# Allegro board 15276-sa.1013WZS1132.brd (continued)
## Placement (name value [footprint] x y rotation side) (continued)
U3602  LR9102G-15-AE5-R-GP  [SOT-23-2924-5PH46]  150.86 25.41 180 bottom
U3603  G5016KD1U-GP  [DFN14J3020-G255D85H32]  145.78 77.1 90 bottom
U5201  RT9724GB-GP  [SOT-23-5H51]  103.22 153.2 180 top
U5601  TPS2001CDGNR-GP  [MSOP8-1G189157H43]  166.99 85.1 180 bottom
U5603  TC74VHCT125AFTQK2M-GP  [TSOIC14H48]  33.76 70.37 270 top
USB1  SKT-USB13-111-GP-U  [SKT-USB13-160166-7]  5.27 39.97 90 bottom
WLAN1  SKT-MINI67P-12-GP-U  [NFSA0-S6705-TP40]  168.6 53.77 90 bottom
X601  XTAL-32D768KHZ-67-GP  [SMD49-6914-0403H56]  128.51 106.31 0 bottom
X1902  XTAL-48MHZ-27-GP-U  [OSC-3225-4P-4H36]  111.89 103.26 180 bottom
X3001  XTAL-25MHZ-155-GP  [OSC-3225-4P-3H36]  49 176.41 180 top
XF3101  XFORM-12P-48-GP  [XFORM12A127097H91]  24.21 169.15 90 bottom
XF3102  XFORM-12P-48-GP  [XFORM12A127097H91]  24.21 169.15 270 top

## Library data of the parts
AFTP2501 AFTP2502 AFTP2801-AFTP2803 AFTP2901-AFTP2904 AFTP3101-AFTP3108 AFTP3301-AFTP3310 AFTP3401-AFTP3403 AFTP3801-AFTP3803 AFTP3805 AFTP3806 AFTP3901-AFTP3910 AFTP5201-AFTP5214 AFTP5227 AFTP5601 AFTP5801-AFTP5807 AFTP6101-AFTP6104 AFTP6201-AFTP6203 AFTP6206-AFTP6208 AFTP6213-AFTP6242 AFTP6245-AFTP6248 AFTP6301-AFTP6307 AFTP6309-AFTP6311 AFTP6313 AFTP6314 = AFTE14P-75: tolerance: ZZ.AFT14.101
BATT1 = 200277MR008G121ZR-U: tolerance: 20.81153.008
C1-C3 = HOLE197R166: tolerance: ZZ.00PAD.V71
C303-C306 C443 C3202 C3205 C3301 C3403-C3406 C3519 C5401 C5604 C5606 C5801-C5804 C6205 EC6106 EC6107 PC4508 PC4516 PC4607 PC4619 = C402H22: tolerance: 78.10421.2FL
C401 C402 C601 = C402H22: tolerance: 78.15124.2FL
C501 C1201 C1204 C1214 C1217 C1222-C1225 C1330 C1334-C1337 C1342 C1344 C1346 C2402-C2404 C2406-C2410 C2412 C2414 C2417 C2502 C2602 C2605 C2608-C2610 C2615 C2707 C2709 C2710 C2717 C2719 C2720 C3002 C3009 C3013 C3014 C3016 C3507 C3625 C3626 C5201 C5203 C5209-C5213 C5402-C5409 C6202-C6204 EC2601 EC2703 EC2705 EC2708 EC2709 EC9739 EC9743 EC9744 PC4906 = C402H22: tolerance: 78.10423.2FL
C502 C1203 C1205 C1221 C1307 C1333 C1345 C3601 C3602 C3618 C3619 C5202 EC2704 EC2706 EC2707 EC6101 EC9707 EC9709-EC9711 EC9714 EC9745 PC4601 PC4605 PC4606 PC4622 PC4660 PC4742 PC4743 PC4831 = C402H22: tolerance: 78.10224.2FL
C603 C604 C3001 C3011 = C402H22: tolerance: 78.15034.1FL
C701 C702 C705 C3505 C3508 C3510 PC4901 PC4904 = C603H36: tolerance: 78.10523.5BL
C703 C762 C1208 C1331 C2501 C2601 C2712 C2713 C2901 C2907 C2908 C3603 C3605 C3620 C3621 C5805 C5806 PC4916 PC4917 PC5010-PC5012 PC5015 = C603H38: tolerance: 78.10610.5BL
C704 C1004-C1009 C1012-C1014 C1026-C1032 C1035-C1037 C1040-C1045 C1093-C1096 C1209-C1212 C1338-C1341 C2416 C2418 C5206 EC9718-EC9728 EC9732-EC9738 EC9759-EC9762 PC5013 = C402H22: tolerance: 78.10520.5FL
C1001 C1002 C1023 C1024 C2703 C2704 C3015 C3018 C3201 C3206 C3520 C3607 C3612 C3613 C3617 PC4829 PC5005 = C402H22: tolerance: 78.10523.5FL
C1003 C1011 C1022 C1025 C1034 C1039 C1049-C1051 C1067 C1080 C1092 = C402H22: tolerance: 78.18134.1FL
C1010 C1015 C1016 C1033 C1038 C1046 C1053-C1055 C1215 C1216 C1218-C1220 C1326-C1329 C1343 C2604 C2611 C2701 C2702 C2706 C2708 C2711 C2715 C2716 C2718 C3004 C3005 C3010 C3012 C3203 C3302 C5204 C5207 PC4920 = C603H36: tolerance: 78.47520.5BL
C1017 C1056-C1063 C3003 C3007 C3008 C3017 C3019 C3021-C3025 PC4604 PC4834 PC4903 PC4915 PC4921 = C402H20: tolerance: 78.10423.5FL
C1047 C1064-C1066 C1068-C1075 C1077 C1081-C1090 C1097-C1101 C1105-C1107 C1113-C1115 = C603H40: tolerance: 78.22610.5BL
C1202 C1306 C2705 = C402H22: tolerance: 78.22510.5FL
C1213 C1332 = C603H36: tolerance: 78.47520.L0L
C1904 C1905 = C402H22: tolerance: 78.6R864.1FL
C2405 C2411 C2413 PC4608 = C603H36: tolerance: 78.22523.5BL
C2415 EC6103 EC6105 = C402H22: tolerance: 78.22124.2FL
C2421 = C402H22: tolerance: 78.47034.1FL
C2503 PC4210 = C402H22: tolerance: 78.47420.5FL
C2603 C2607 EC4401 PC4611 PC4626 = C402H22: tolerance: 78.22224.2FL
C2606 = C603H36: tolerance: 78.47134.1BL
C2616 EC2905-EC2908 PC4615 PC4617 = C402H22: tolerance: 78.10134.1FL
C2723 EC5205 EC5206 PC5014 = C402H22: tolerance: 78.22034.1FL
C3101 = C1808H56: tolerance: 78.1013N.1AL
C3106 C3204 C5602 C5603 C5607 C5608 C5611 C5612 C5615 C5616 PC4203-PC4205 PC4209 PC4412 PC4425 PC4609 PC4614 PC4616 = C402H22: tolerance: 78.10324.2FL
C3303 C5601 C5605 C5609 C5610 = C805H54: tolerance: 78.10623.51L
C3401 C3402 EC2501 EC2502 = C402H22: tolerance: 78.4R774.1FL
C3512 C3513 C3521 PC4923-PC4926 = C805H58: tolerance: 78.22610.51L
C5205 EC4304 EC4601 PC4401 = C603H36: tolerance: 78.10422.2BL
C5208 C5214 C5506 C5539-C5543 EC2503 EC2602 EC2701 EC3101-EC3108 EC4301 EC4302 EC4305 PC4612 PC4627 = C402H22: tolerance: 78.10034.1FL
C5508 C5511 = C402H22: tolerance: 78.10134.L1L
C5509 C5510 PC4506 PC4521 PC4832 = C402H22: tolerance: 78.18034.1FL
C5519 PC4902 = C402H22: tolerance: 78.10321.2FL
CARD1 = CS1S-461HN: tolerance: 20.I0147.001
CN6301 = 196246-24021: tolerance: 20.K0846.024
CPU1 = BGA769M24D5H78: tolerance: 071.BEEMA.000U
D401 D3602 = SOT23-2D4-312H44: tolerance: 83.00016.P11
D2401 D3606 = SOD323AKH38: tolerance: 83.R2004.G8F
D2501 = SOT23-2D4-312H48: tolerance: 75.00040.A7D
D2601 D5202 D5501 = SOD323AKH38: tolerance: 83.R5003.H8H
D2701 D5201 = SOT23-2D6-312H46: tolerance: 75.00054.K7D
D3603 = SOT23-2D4-312H44: tolerance: 83.00016.K11
D4301-D4303 PD4203 = SOT23-2D4-312H44: tolerance: 75.00099.O7D
D5401 = SOT-23-9H44: tolerance: 83.00056.Q11
DB1 = 87212-1002N: tolerance: 20.F1180.010
DCIN1 = 50458-00601-W01: tolerance: 20.F2132.006
DM1 = 80001-1921: tolerance: 62.10017.X41
DM2 = AS0A621-J4SB-7H: tolerance: 62.10024.S11
EC2901-EC2904 = C603: tolerance: 78.22224.2BL
EC3201 = C402H22: tolerance: 78.6R074.1FL
EC3301-EC3307 = C402H22: tolerance: 78.4R7B4.1FL
EC4201 EC4303 EC4402 EC9701 EC9703-EC9705 EC9708 EC9712 EC9713 EC9715-EC9717 EC9740-EC9742 EC9746-EC9758 PC4402 PC4420 PC4421 PC4423 = C402H22: tolerance: 78.10422.5FL
EC4202 PC4206 PC4406 PC4415-PC4418 PC4426 PC4507 PC4514 PC4528-PC4530 PC4713 PC4715-PC4719 PC4721 PC4830 PC4912 = C805H56: tolerance: 78.10622.51L
EC4203 = C805H38: tolerance: 78.10434.21L
EC5210 EC5801 EC5802 EC6205-EC6208 = C402H22: tolerance: 78.33034.1FL
ED2401-ED2403 = D402H24: tolerance: 83.05325.AA0
ED6101 = SOD882-10D6-1H20: tolerance: 83.05725.0A0
EL4201-EL4203 = PAD-2P-4516-U: tolerance: ZZ.00PAD.V91
EU3403 EU3404 = SOT-6H58: tolerance: 75.09904.07C
EU5602 U3402 = DFN10G2510H26: tolerance: 75.01045.073
F5201 F5203 = POLYSW-4633-UH43: tolerance: 69.50007.A31
F5501 = POLYSW-2114H30: tolerance: 69.48001.081
F6201 = POLYSW-2114H50: tolerance: 69.50007.921
FAN1 = 3703K-Q03N-11L: tolerance: 20.F1841.003
FAN261 = SOIC8H69: tolerance: 74.05606.A71
G701 G6101 G6102 = CON2O-U: tolerance: ZZ.CON2O.XXX
H1 = HOLE256R126: tolerance: ZZ.00PAD.Z61
H2-H5 = HOLE335R115: tolerance: ZZ.00PAD.D01
H7 = HOLE296R182: tolerance: ZZ.00PAD.Y51
HDA27 = QFN48J6-G465H40: tolerance: 71.03234.003
HDD1 = 132F12-010000-A2-R: tolerance: 020.K0125.0012
HDLED1 = LED3015-1A2K-3PH44: tolerance: 83.01221.R70
HDMI1 = PAD-D-SUB-HDMI-COLAY-U: tolerance: ZZ.00PAD.BI1
HDT1 = ASP-137098-05: tolerance: 20.F1722.020
KB1 = FL4S030HT6R300-DT: tolerance: 20.K0592.030
KBC24 = LQFP128H63: tolerance: 071.00285.000G
KBLIT1 = 51575-00401-W01: tolerance: 20.K0800.004
L3001 = L2520-D820H41: tolerance: 68.4R71E.10G
L5507-L5509 = L1608-UH38: tolerance: 68.00084.A11
LCD1 = 51540-04001-W01: tolerance: 20.K0678.040
LED1 = LED3020-3P-19H44: tolerance: 083.1212A.0070
LOM30 = QFN32J4-G2D85H36: tolerance: 71.08111.U03
ODD1 = 51519-02001-W03: tolerance: 20.K0708.020
PC4010 = C603H36: tolerance: 78.47422.5BL
PC4201 = C805H58: tolerance: 78.10594.41L
PC4202 PC4409 PC4419 PC4720 PC4722 PC4827 PC4833 PC4913 PC4919 = C603H36: tolerance: 78.10424.2BL
PC4208 PC4403 PC4404 PC4407 PC4434 PC4602 = C603H36: tolerance: 78.10522.5BL
PC4408 PC4503 PC4504 PC4828 PC4909 PC4911 PC4914 = C805H54: tolerance: 78.47522.51L
PC4411 PC4623 PC4628 = C402H22: tolerance: 78.47322.2FL
PC4413 = C603H36: tolerance: 78.33224.2BL
PC4422 = C402H22: tolerance: 78.22134.1FL
PC4505 PC4510 PC4523-PC4525 = C603H36: tolerance: 78.10424.L0L
PC4603 PC4624 = C402H22: tolerance: 78.33224.2FL
PC4610 PC4648 PC4922 = C402H22: tolerance: 78.33124.2FL
PC4613 PC4618 = C402H22: tolerance: 78.47124.2FL
PC4734 PC4736 = C603H40: tolerance: 78.22422.2BL
PC4838 = C603: tolerance: 78.56124.2BL
PC4918 = C402H22: tolerance: 78.22423.5FL
PC5020 = C402H22: tolerance: 78.68124.2FL
PD4201 = DO214AAAKH97: tolerance: 83.P6SMB.JAG
PD4204 = SOT-23-10H44: tolerance: 83.0024V.0A1
PD4302 = SOD123FLAKH40: tolerance: 83.SMF18.0AH
PD4401 = SOD323AKH42: tolerance: 83.1R504.A8F
PD4404 = SOD323AKH42: tolerance: 83.04148.D1H
PG4402 PG4403 PG4407-PG4415 PG4502-PG4505 PG4511-PG4531 PG4535 PG4701-PG4704 PG4707-PG4712 PG4716-PG4720 PG4824-PG4828 PG4830-PG4832 PG4834 PG4837 PG4838 PG4901-PG4911 PG4913-PG4919 PG5009-PG5014 = GAP-CLOSE-PWR-3: tolerance: ZZ.CLOSE.001
PG4537 PG4538 PG4543 PG4547 = GAP-CLOSE-PWR: tolerance: ZZ.CLOSE.011
PL4401 = L686647-127318H119: tolerance: 68.5R610.10U
PL4503 PL4504 = L686647-127318H119: tolerance: 68.2R21B.10J
PL4701 PL4702 = L7066-1830-UH158: tolerance: 68.R3610.20W
PL4802 PL5002 = L7066-1830-UH119: tolerance: 68.2R210.20B
PL4902 = L7066-1830-UH119: tolerance: 68.R6810.20B
PQ4201 = SOT23DGS2D4H44: tolerance: 84.00301.A31
PQ4202 Q2603 Q3002 Q3003 = SOT23CBE2D6H46: tolerance: 84.03904.P11
PQ4203 PQ4206 PQ4402 PQ4407 PQ4408 PQ4410 Q403 Q601 Q603 Q2601 Q5402 Q5502 Q6202 = SOT-363H44: tolerance: 84.2N702.A3F
PQ4204 = SOT323CBE2D2H40: tolerance: 84.05212.B11
PQ4205 = SOT323EBC2D2H40: tolerance: 084.05112.001K
PQ4208 Q701 Q2401 Q2403 Q2505 Q2602 Q3001 Q5403 Q6105 Q6107 Q6205 = SOT23DGS2D4H44: tolerance: 84.2N702.J31
PQ4409 Q2404 = SOT23CBE2D4H44: tolerance: 84.T3906.A11
PR3622 PR4203 PR4211 PR4835 R601 R603 R604 R608 R617 R620 R621 R627 R630-R635 R637-R641 R644 R649-R651 R701 R702 R1913 R1918 R1920 R1931 R2401 R2412 R2414 R2415 R2418 R2436 R2439 R2441 R2443 R2501 R2919 R2920 R3003 R3004 R3021 R3033 R5208 R5604 R5812 R6110 R6203 = R402H16: tolerance: 63.10334.1DL
PR4202 PR4514 = R402H16: tolerance: 64.15025.6DL
PR4204 = R402H16: tolerance: 63.22234.1DL
PR4205 R616 R1925 R2420 = R402H16: tolerance: 63.33034.1DL
PR4207 = R603H22: tolerance: 63.24434.15L
PR4208 = R603H22: tolerance: 63.47333.15L
PR4209 PR4212 PR4213 PR4216 PR4218 PR4403 PR4417 PR4419 PR4425 PR4428 PR4430 PR4434 PR4438 PR4469 PR4510 R626 R629 R642 R643 R648 R2413 R2421 R2426 R2429 R2437 R2442 R2445 R2711 R2722 R3023 R3501 R3625 R3626 R5202 R5412 R5413 R5610 R6207 R6208 = R402H16: tolerance: 63.10434.1DL
PR4210 PR4215 R403 R410 R411 R413 R415 R416 R422-R426 R429 R434 R504 R628 R2432 R2447 R2452 R2453 R2502 R2717 R2921 R2922 R3014 R3603 R3624 R6201 = R402H16: tolerance: 63.10234.1DL
PR4214 = R1206H28: tolerance: 63.33232.11L
PR4217 PR4911 R2402 R3016 R5230 = 0R0603-PAD-1-U: tolerance: ZZ.00PAD.M21
PR4401 PR4435 PR4439 PR4473 PR4518 PR4523 PR4614 PR4615 PR4636 PR4903 R2404 R2449 = R402H16: tolerance: 64.10025.6DL
PR4402 PR4416 = R3720H40: tolerance: 64.R0105.7FL
PR4404 = R805H24: tolerance: 63.30231.16L
PR4405 = R402H16: tolerance: 63.47434.1DL
PR4406 PR4418 PR4466 PR4468 PR4475 PR4476 PR4506 PR4513 PR4526-PR4531 PR4601 PR4603 PR4617 PR4621 PR4651-PR4653 R409 R414 R602 R609 R611-R614 R618 R622 R625 R1901 R1906-R1908 R1921-R1924 R1930 R2408-R2411 R2416 R2419 R2422-R2424 R2434 R2440 R2444 R2448 R2450 R2454 R2601 R2602 R2605 R2606 R2612 R2701 R2705 R2712 R2714 R2716 R2718-R2721 R2723 R3002 R3201 R3202 R3204 R3205 R3401 R3402 R3408-R3415 R3604 R3605 R3609 R3627 R5203-R5207 R5209 R5212 R5222 R5401-R5408 R5418 R5419 R5448 R5449 R5602 R5605 R5801-R5808 R5810 R5811 R6104-R6106 R6215 R6217 R6301 R6302 R6501 R6502 = R402H16: tolerance: 63.R0034.1DL
PR4407 = R402H16: tolerance: 64.30935.6DL
PR4408 = R805H24: tolerance: 63.10031.16L
PR4409 R703 R2607 R2703 R2901-R2904 R2906 R2907 R2909 R2911 R2923 R3001 R3006 R5229 R5231 R5232 R5506 R6205 R6209 R6216 R6305 = R603H22: tolerance: 63.00000.00L
PR4411 PR5009 = R402H16: tolerance: 64.10235.6DL
PR4412 PR4415 = R402H16: tolerance: 64.33015.6DL
PR4413 = R402H16: tolerance: 64.84525.6DL
PR4414 = R402H16: tolerance: 63.33534.1DL
PR4420 = R402H16: tolerance: 64.7R505.6DL
PR4421 PR4632 PR4639 R2908 R2910 = R402H14: tolerance: 64.10R05.6DL
PR4422 PR4426 PR4607 PR4609 PR4613 PR4616 PR4819 PR4821 PR4906 PR4907 PR4910 PR5010 R404 R412 R417 R418 R2417 R2427 R2428 R2430 R2435 R2438 R2708 R3005 R5201 R6202 R6210-R6213 = 0R0402-PAD-1: tolerance: ZZ.00PAD.M11
PR4423 = R402H16: tolerance: 64.59025.6DL
PR4424 = R402H16: tolerance: 64.84515.6DL
PR4427 = R402H16: tolerance: 64.66525.6DL
PR4429 PR4817 R5411 = R402H16: tolerance: 64.15035.6DL
PR4431 = R402H16: tolerance: 64.47025.6DL
PR4432 PR4433 PR4436 = R402H16: tolerance: 64.12035.6DL
PR4437 = R402H16: tolerance: 64.16035.6DL
PR4464 = R402H16: tolerance: 63.68434.1DL
PR4467 R1905 = R402H16: tolerance: 63.10534.1DL
PR4470 PR4902 PR5011 R2406 R2407 = R402H16: tolerance: 64.10035.6DL
PR4505 PR4524 = R603H22: tolerance: 64.1R505.55L
PR4507 = R402H16: tolerance: 64.11035.6DL
PR4511 = R402H16: tolerance: 64.28735.6DL
PR4516 = R402H16: tolerance: 64.66515.6DL
PR4602 PR4604 PR4620 R5210 R5233 R6102 R6109 = R402H14: tolerance: 63.10134.1DL
PR4605 PR4618 = NTC-402H22-U: tolerance: 69.60037.031
PR4606 PR4619 PR4904 R2433 R2707 R6218 = R402H16: tolerance: 64.20025.6DL
PR4608 = R402H16: tolerance: 64.30005.6DL
PR4610 = R402H16: tolerance: 64.2R005.6DL
PR4611 = R402H16: tolerance: 64.54925.6DL
PR4612 PR4622 PR4627 PR4641 PR4649 PR4660 PR4661 R301 R1903 R1904 R1909 R1910 = R402H16: tolerance: 64.10015.6DL
PR4623 PR4650 = R402H16: tolerance: 64.49R95.6DL
PR4624 PR4647 = R402H16: tolerance: 64.82015.6DL
PR4625 PR4646 = R402H16: tolerance: 64.26125.6DL
PR4626 = R402H16: tolerance: 64.22625.6DL
PR4628 PR4634 PR4638 PR4645 PR4648 = R402H16: tolerance: 64.13035.6DL
PR4629 PR4642 = R402H16: tolerance: 64.75025.6DL
PR4630 PR4643 = R402H16: tolerance: 64.49935.6DL
PR4631 PR4637 = R402H16: tolerance: 64.54915.6DL
PR4633 PR4644 = R603H22: tolerance: 64.69825.55L
PR4635 = R402H16: tolerance: 64.24025.6DL
PR4640 PR4901 = R402H16: tolerance: 64.30125.6DL
PR4677 PR4678 = NTC-402H22-U: tolerance: 69.60011.081
PR4701 PR4702 PR4820 PR4905 R2403 = R603H22: tolerance: 64.2R205.55L
PR4709 PR4710 = R1206H28: tolerance: 63.2R232.11L
PR4822 R1902 = R402H16: tolerance: 64.11825.6DL
PR4823 = R402H16: tolerance: 64.33025.L0L
PR4824 = R402H16: tolerance: 64.47035.6DL
PR4837 PR4912 = R805H24: tolerance: 64.2R205.16L
PR4908 = R402H16: tolerance: 64.12025.6DL
PR5012 = R402H16: tolerance: 64.2R205.6DL
PR5013 = R402H16: tolerance: 64.51025.6DL
PR5020 = R402H16: tolerance: 64.18025.6DL
PT4701 PT4704 PT4803 = SE361414H178: tolerance: 79.3371V.6CL
PT4702 PT4703 = CT7343H83: tolerance: 79.33719.L01
PT4705 PT4706 = SE361413H182: tolerance: 79.33612.6CL
PU4201 PU4402 PU4403 = PPAK-8P-3232H36: tolerance: 84.07401.037
PU4404 = QFN20G3D5-G2D15H40: tolerance: 74.24727.A73
PU4405 PU4406 PU4506 PU4508 PU4510 PU4805 PU4808 PU4902 PU4903 = PPAK-8P-2H45: tolerance: 84.00412.037
PU4507 = PPAK-8P-2H45: tolerance: 84.00780.037
PU4509 = QFN20-G1D75H32: tolerance: 074.06575.0A43
PU4601 = LFQFN52J6-G4D8-1H40: tolerance: 074.81128.0073
PU4701 PU4703 PU4707 = PPAK-5PH45: tolerance: 84.A14DP.037
PU4702 PU4704 PU4706 PU4708 = PPAK-5PH45: tolerance: 84.SRA12.037
PU4806 = DFN10G3-G265175H32: tolerance: 74.08237.B73
PU4901 = QFN20-G1D75H32: tolerance: 74.51716.073
PU5002 = DFN10G3-G265175H32: tolerance: 74.08068.A43
PWR1 = 6916K-Q04M-00L: tolerance: 20.K0465.004
Q2402 Q3004 Q6204 = SOT23DGS2D4H48: tolerance: 84.02130.031
Q5401 = SOT23CBE2D4H44: tolerance: 84.T3904.H11
Q6103 Q6104 Q6106 Q6201 = SOT23CBE2D6H62: tolerance: 084.02418.0011
Q6203 = SOT23DGS2D8H56: tolerance: 84.P8503.031
R302 = R402H16: tolerance: 64.16915.6DL
R401 R405 R406 R408 R5523-R5525 = R402H16: tolerance: 64.15005.6DL
R402 R2604 R2624 = R402H16: tolerance: 64.20015.6DL
R407 R6103 = R402H16: tolerance: 64.49905.6DL
R419 R420 = R402H16: tolerance: 64.51105.6DL
R421 = R402H16: tolerance: 63.30134.1DL
R503 = R402H16: tolerance: 64.39R25.6DL
R623 = R603H22: tolerance: 63.20634.15L
R645-R647 R3015 = R402H16: tolerance: 63.15334.1DL
R1301 R2912 R2913 = R402H16: tolerance: 63.47234.1DL
R1911 R1915 R1927 R1929 = R402H15: tolerance: 63.10334.L0L
R1912 R1914 R1916 R1917 R1919 R1926 R1928 = R402H16: tolerance: 63.20234.1DL
R2405 = R402H16: tolerance: 64.27025.6DL
R2425 R2431 = R402H16: tolerance: 63.33434.1DL
R2446 = R402H16: tolerance: 64.32425.6DL
R2451 = R402H16: tolerance: 64.13725.6DL
R2504 = R402H16: tolerance: 63.10634.1DL
R2603 = R402H16: tolerance: 64.18725.6DL
R2610 = NTC-603H38: tolerance: 69.60035.041
R2611 R2622 = R402H16: tolerance: 64.24325.6DL
R2702 R2704 R5211 R5601 R5603 R5809 = R805H24: tolerance: 63.R0031.16L
R2706 = 0R0805-PAD-1-U: tolerance: ZZ.00PAD.M31
R2709 R5410 = R402H16: tolerance: 64.20035.6DL
R3022 = R402H16: tolerance: 63.20334.1DL
R3032 = R402H16: tolerance: 64.24915.6DL
R3203 = R402H16: tolerance: 64.62015.6DL
R3301 = 0R0402-PAD: tolerance: ZZ.R0402.ZZZ
R3602 = R402H16: tolerance: 63.20434.1DL
R5414-R5417 = R402H16: tolerance: 63.15134.1DL
R5526 R5527 = R402H15: tolerance: 63.33034.L0L
R6101 R6108 = R402H16: tolerance: 63.33134.1DL
R6206 = R402H16: tolerance: 63.51334.1DL
R6214 = R603H22: tolerance: 63.10133.15L
RJ45 = C100PF-10809-L: tolerance: 022.10001.0C41
RN401 RN601 RN2602 RN2901 RN5401 RN5404 RN5508 = ARES2H16: tolerance: 66.22236.04L
RN402 RN2401 RN5509 RN6201 = SMD-ARES4H18: tolerance: 66.47236.04L
RN404 RN405 RN407 = ARES8-CN24H20: tolerance: 66.10236.08L
RN408 = SMD-ARES4-2H18-U: tolerance: 66.1023A.04L
RN602 = SMD-ARES4: tolerance: 66.10436.04L
RN603 RN1904 RN2501 RN3001 RN5601 RN6203 = ARES2H18: tolerance: 66.10336.04L
RN1901 RN6501 = ARES8-CN24H22: tolerance: 66.R0036.A8L
RN1902 RN1903 RN2601 = SMD-ARES4H20: tolerance: 66.R0036.04L
RN3101 = ARES8-CN24H22: tolerance: 66.75036.08L
RN4301 RN5201 = ARES8-CN24H20: tolerance: 66.10136.A8L
RN5203 = ARES8-CN24H20: tolerance: 66.10436.A8L
RN5204 RN5506 RN5507 = SMD-ARES4H18: tolerance: 66.33036.04L
RN5402 RN5403 = ARES8-CN24H20: tolerance: 66.49156.08L
RN6502 = ARES8-CN24-MUH20: tolerance: 66.10336.08L
RTC1 = 060003HA002M213ZL-U2: tolerance: 62.70014.001
SPI25 = SOIC8-1H86: tolerance: 72.25Q64.K01
SPK1 = 50224-0040N-001: tolerance: 20.F1639.004
SPR1 = SPR6035H166: tolerance: 34.49U24.001
SPR2 = SPR5930H154: tolerance: 34.41V01.001
SPR3 = SPR7837H229: tolerance: 34.43E24.001
SPR4 = SPR6438H83: tolerance: 34.49U26.001
SSKT2 = G6179HT0321-001: tolerance: 62.10089.011
TC3501 = C1206H71: tolerance: 78.10710.52L
TC4501 TC4503 = SE361416H178: tolerance: 77.52271.09L
THM26 = MSOP8-1H44: tolerance: 74.83771.ABG
TP401-TP404 TP409-TP411 TP416-TP418 TP420-TP423 TP433 TP434 TP1901 TP1903 TP1904 TP2401 TP2402 TP2702 TP3001-TP3003 TP3201 TP5801-TP5804 = TPAD14-OP: tolerance: ZZ.PAD14.001
TPAD1 = 50505-0084N-002: tolerance: 20.K0667.008
TR3401 TR3402 = L125100-4P-1H37: tolerance: 68.11350.201
TR3404-TR3406 TR5209 TR5801 = L125100-4P-4H28: tolerance: 68.01012.20B
U402 = SC70-6H44: tolerance: 73.7WV07.00J
U701 = SOT23-2D8-312H58: tolerance: 74.02138.03B
U3101 U3102 = DFN10G2510H26: tolerance: 75.01004.073
U3201 = QFN24-G2D5H40-U: tolerance: 71.05170.003
U3503 U3504 = SOT-23-5H58: tolerance: 074.00524.0C9F
U3601 U3603 = DFN14J3020-G255D85H32: tolerance: 074.05016.0093
U3602 = SOT-23-2924-5PH46: tolerance: 074.09102.003F
U5201 = SOT-23-5H51: tolerance: 74.09724.09F
U5601 = MSOP8-1G189157H43: tolerance: 74.02001.079
U5603 = TSOIC14H48: tolerance: 73.74125.F0B
USB1 = SKT-USB13-160166-7: tolerance: 22.10339.S21
WLAN1 = NFSA0-S6705-TP40: tolerance: 062.10007.0081
X601 = SMD49-6914-0403H56: tolerance: 82.30001.G11
X1902 = OSC-3225-4P-4H36: tolerance: 82.30026.281
X3001 = OSC-3225-4P-3H36: tolerance: 82.30020.D41
XF3101 XF3102 = XFORM12A127097H91: tolerance: 68.68167.30D

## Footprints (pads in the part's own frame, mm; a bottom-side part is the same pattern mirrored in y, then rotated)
0R0402-PAD
  custom 0.14x0.14 smd: 1(0,0.445) 2(0,-0.445)
0R0402-PAD-1
  custom 0.14x0.14 smd: 1(0,0.445) 2(0,-0.445)
0R0603-PAD-1-U
  custom 0.254x0.254 smd: 1(0,0.66) 2(0,-0.66)
0R0805-PAD-1-U
  rect 1.549x1.333 smd: 1(0,0.838) 2(0,-0.838)
132F12-010000-A2-R
  rect 0.305x0.838 smd: 1(-2.75,3.175) 2(-2.25,3.175) 3(-1.75,3.175) 4(-1.25,3.175) 5(-0.75,3.175) 6(-0.25,3.175) 7(0.25,3.175) 8(0.75,3.175) 9(1.25,3.175) 10(1.75,3.175) 11(2.25,3.175) 12(2.75,3.175)
  rect 1.448x2.007 smd: 13(-5.125,0) 14(5.125,0)
3703K-Q03N-11L
  rect 0.61x1.549 smd: 1(-1,3.775) 2(0,3.775) 3(1,3.775)
  rect 1.194x2.007 smd: 4(-2.3,0) 5(2.3,0)
6916K-Q04M-00L
  rect 0.305x1.295 smd: 1(-1.5,2.65) 2(-0.5,2.65) 3(0.5,2.65) 4(1.5,2.65)
  rect 1.803x1.397 smd: 5(-3.65,0) 6(3.65,0)
50224-0040N-001
  rect 0.61x1.549 smd: 1(-1.5,3.875) 2(-0.5,3.875) 3(0.5,3.875) 4(1.5,3.875)
  rect 1.194x1.803 smd: 5(-2.797,0) 6(2.797,0)
50458-00601-W01
  rect 0.559x1.295 smd: 1(5,5.025) 2(3,5.025) 3(1,5.025) 4(-1,5.025) 5(-3,5.025) 6(-5,5.025)
  rect 1.295x2.057 smd: 7(8.1,0) 8(-8.1,0)
50505-0084N-002
  rect 0.406x1.295 smd: 1(3.5,3.25) 2(2.5,3.25) 3(1.5,3.25) 4(0.5,3.25) 5(-0.5,3.25) 6(-1.5,3.25) 7(-2.5,3.25) 8(-3.5,3.25)
  rect 0.991x2.007 smd: 9(6.1,0) 10(-6.1,0)
51519-02001-W03
  rect 0.305x1.295 smd: 1(-4.75,5.65) 2(-4.25,5.65) 3(-3.75,5.65) 4(-3.25,5.65) 5(-2.75,5.65) 6(-2.25,5.65) 7(-1.75,5.65) 8(-1.25,5.65) 9(-0.75,5.65) 10(-0.25,5.65) 11(0.25,5.65) 12(0.75,5.65) 13(1.25,5.65) 14(1.75,5.65) 15(2.25,5.65) 16(2.75,5.65) 17(3.25,5.65) 18(3.75,5.65) 19(4.25,5.65) 20(4.75,5.65)
  rect 1.803x2.21 smd: 21(-6.9,0) 22(6.9,0)
51540-04001-W01
  rect 0.305x0.838 smd: 1(-9.75,3.175) 2(-9.25,3.175) 3(-8.75,3.175) 4(-8.25,3.175) 5(-7.75,3.175) 6(-7.25,3.175) 7(-6.75,3.175) 8(-6.25,3.175) 9(-5.75,3.175) 10(-5.25,3.175) 11(-4.75,3.175) 12(-4.25,3.175) 13(-3.75,3.175) 14(-3.25,3.175) 15(-2.75,3.175) 16(-2.25,3.175) 17(-1.75,3.175) 18(-1.25,3.175) 19(-0.75,3.175) 20(-0.25,3.175) 21(0.25,3.175) 22(0.75,3.175) 23(1.25,3.175) 24(1.75,3.175) 25(2.25,3.175) 26(2.75,3.175) 27(3.25,3.175) 28(3.75,3.175) 29(4.25,3.175) 30(4.75,3.175) 31(5.25,3.175) 32(5.75,3.175) 33(6.25,3.175) 34(6.75,3.175) 35(7.25,3.175) 36(7.75,3.175) 37(8.25,3.175) 38(8.75,3.175) 39(9.25,3.175) 40(9.75,3.175)
  rect 0.813x2.007 smd: 41(-11.45,0) 42(11.45,0)
51575-00401-W01
  rect 0.406x0.838 smd: 1(-1.5,3.175) 2(-0.5,3.175) 3(0.5,3.175) 4(1.5,3.175)
  rect 0.813x2.007 smd: 5(-3.7,0) 6(3.7,0)
060003HA002M213ZL-U2
  round 0.254 hole 1.219 unplated: (0,-8)
  round 0.254 hole 1.321 unplated: (0,8)
  custom 1.454x1.454 smd: 1(14.5,0)
  custom 1.899x1.899 smd: 2(-15.8,0)
80001-1921
  round 0.254 hole 1.118 unplated: (-33.4,0)
  round 0.254 hole 1.6 unplated: (33.4,0)
  custom 0.114x0.114 smd: 1(31.65,4.1) 2(31.35,-4.1) 3(31.05,4.1) 4(30.751,-4.1) 5(30.45,4.1) 6(30.15,-4.1) 7(29.85,4.1) 8(29.55,-4.1) 9(29.251,4.1) 10(28.95,-4.1) 11(28.65,4.1) 12(28.35,-4.1) 13(28.051,4.1) 14(27.751,-4.1) 15(27.45,4.1) 16(27.15,-4.1) 17(26.851,4.1) 18(26.551,-4.1) 19(26.25,4.1) 20(25.95,-4.1) 21(25.65,4.1) 22(25.35,-4.1) 23(25.051,4.1) 24(24.75,-4.1) 25(24.45,4.1) 26(24.15,-4.1) 27(23.851,4.1) 28(23.55,-4.1) 29(23.25,4.1) 30(22.95,-4.1) 31(22.651,4.1) 32(22.351,-4.1) 33(22.05,4.1) 34(21.75,-4.1) 35(21.451,4.1) 36(21.151,-4.1) 37(20.85,4.1) 38(20.55,-4.1) 39(20.25,4.1) 40(19.95,-4.1) 41(19.65,4.1) 42(19.35,-4.1) 43(19.049,4.1) 44(18.749,-4.1) 45(18.45,4.1) 46(18.15,-4.1) 47(17.85,4.1) 48(17.549,-4.1) 49(17.25,4.1) 50(16.95,-4.1) 51(16.65,4.1) 52(16.349,-4.1) 53(16.049,4.1) 54(15.75,-4.1) 55(15.45,4.1) 56(15.15,-4.1) 57(14.849,4.1) 58(14.549,-4.1) 59(14.25,4.1) 60(13.95,-4.1) 61(13.649,4.1) 62(13.349,-4.1) 63(13.05,4.1) 64(12.75,-4.1) 65(12.45,4.1) 66(12.149,-4.1) 67(11.85,4.1) 68(11.55,-4.1) 69(11.25,4.1) 70(10.95,-4.1) 71(10.649,4.1) 72(10.349,-4.1) 73(7.65,4.1) 74(7.35,-4.1) 75(7.049,4.1) 76(6.749,-4.1) 77(6.45,4.1) 78(6.15,-4.1) 79(5.85,4.1) 80(5.549,-4.1) 81(5.25,4.1) 82(4.95,-4.1) 83(4.65,4.1) 84(4.349,-4.1) 85(4.05,4.1) 86(3.75,-4.1) 87(3.45,4.1) 88(3.15,-4.1) 89(2.849,4.1) 90(2.549,-4.1) 91(2.25,4.1) 92(1.95,-4.1) 93(1.649,4.1) 94(1.349,-4.1) 95(1.05,4.1) 96(0.75,-4.1) 97(0.45,4.1) 98(0.149,-4.1) 99(-0.15,4.1) 100(-0.45,-4.1) 101(-0.75,4.1) 102(-1.051,-4.1) 103(-1.351,4.1) 104(-1.65,-4.1) 105(-1.95,4.1) 106(-2.25,-4.1) 107(-2.551,4.1) 108(-2.851,-4.1) 109(-3.15,4.1) 110(-3.45,-4.1) 111(-3.751,4.1) 112(-4.051,-4.1) 113(-4.35,4.1) 114(-4.65,-4.1) 115(-4.95,4.1) 116(-5.251,-4.1) 117(-5.55,4.1) 118(-5.85,-4.1) 119(-6.15,4.1) 120(-6.451,-4.1) 121(-6.751,4.1) 122(-7.051,-4.1) 123(-7.35,4.1) 124(-7.65,-4.1) 125(-7.951,4.1) 126(-8.251,-4.1) 127(-8.55,4.1) 128(-8.85,-4.1) 129(-9.15,4.1) 130(-9.451,-4.1) 131(-9.75,4.1) 132(-10.05,-4.1) 133(-10.35,4.1) 134(-10.651,-4.1) 135(-10.95,4.1) 136(-11.25,-4.1) 137(-11.55,4.1) 138(-11.85,-4.1) 139(-12.151,4.1) 140(-12.451,-4.1) 141(-12.75,4.1) 142(-13.05,-4.1) 143(-13.351,4.1) 144(-13.651,-4.1) 145(-13.95,4.1) 146(-14.25,-4.1) 147(-14.55,4.1) 148(-14.851,-4.1) 149(-15.15,4.1) 150(-15.45,-4.1) 151(-15.75,4.1) 152(-16.051,-4.1) 153(-16.35,4.1) 154(-16.65,-4.1) 155(-16.95,4.1) 156(-17.25,-4.1) 157(-17.551,4.1) 158(-17.851,-4.1) 159(-18.15,4.1) 160(-18.45,-4.1) 161(-18.751,4.1) 162(-19.051,-4.1) 163(-19.35,4.1) 164(-19.65,-4.1) 165(-19.95,4.1) 166(-20.251,-4.1) 167(-20.55,4.1) 168(-20.85,-4.1) 169(-21.15,4.1) 170(-21.451,-4.1) 171(-21.751,4.1) 172(-22.051,-4.1) 173(-22.35,4.1) 174(-22.65,-4.1) 175(-22.951,4.1) 176(-23.251,-4.1) 177(-23.55,4.1) 178(-23.85,-4.1) 179(-24.151,4.1) 180(-24.451,-4.1) 181(-24.75,4.1) 182(-25.05,-4.1) 183(-25.35,4.1) 184(-25.651,-4.1) 185(-25.95,4.1) 186(-26.25,-4.1) 187(-26.55,4.1) 188(-26.851,-4.1) 189(-27.151,4.1) 190(-27.451,-4.1) 191(-27.75,4.1) 192(-28.05,-4.1) 193(-28.351,4.1) 194(-28.651,-4.1) 195(-28.95,4.1) 196(-29.25,-4.1) 197(-29.55,4.1) 198(-29.851,-4.1) 199(-30.15,4.1) 200(-30.45,-4.1) 201(-30.75,4.1) 202(-31.05,-4.1) 203(-31.349,4.1) 204(-31.649,-4.1)
  rect 3.505x4.597 smd: 205(32.8,12) 206(-32.8,12)
87212-1002N
  rect 0.61x1.549 smd: 1(-4.5,-2.525) 2(-3.5,-2.525) 3(-2.5,-2.525) 4(-1.5,-2.525) 5(-0.5,-2.525) 6(0.5,-2.525) 7(1.5,-2.525) 8(2.5,-2.525) 9(3.5,-2.525) 10(4.5,-2.525)
  rect 1.194x1.803 smd: 11(-5.797,0) 12(5.797,0)
196246-24021
  rect 0.508x1.295 smd: 1(11.5,2.798) 2(10.5,2.798) 3(9.5,2.798) 4(8.5,2.798) 5(7.5,2.798) 6(6.5,2.798) 7(5.5,2.798) 8(4.5,2.798) 9(3.5,2.798) 10(2.5,2.798) 11(1.5,2.798) 12(0.5,2.798) 13(-0.5,2.798) 14(-1.5,2.798) 15(-2.5,2.798) 16(-3.5,2.798) 17(-4.5,2.798) 18(-5.5,2.798) 19(-6.5,2.798) 20(-7.5,2.798) 21(-8.5,2.798) 22(-9.5,2.798) 23(-10.5,2.798) 24(-11.5,2.798)
  rect 1.803x1.397 smd: 25(13.652,0) 26(-13.652,0)
200277MR008G121ZR-U
  round 1.626 hole 1.219: 1(7,0) 2(5,0) 3(3,0) 4(1,0) 5(-1,0) 6(-3,0) 7(-5,0) 8(-7,0)
  oval 1.727x3.505 hole 1.016x2.794: 9(10.125,0) 10(-10.125,0)
AFTE14P-75
  round 0.356 smd: 1(0,0)
ARES2H16
  rect 0.356x0.66 smd: 1(-0.325,-0.599) 2(0.325,-0.599) 3(0.325,0.599) 4(-0.325,0.599)
ARES2H18
  rect 0.356x0.66 smd: 1(-0.325,-0.599) 2(0.325,-0.599) 3(0.325,0.599) 4(-0.325,0.599)
ARES8-CN24-MUH20
  rect 0.61x0.66 smd: 1(-0.9,-0.486) 4(0.9,-0.486) 5(0.9,0.486) 8(-0.9,0.486)
  rect 0.305x0.66 smd: 2(-0.25,-0.486) 3(0.25,-0.486) 6(0.25,0.486) 7(-0.25,0.486)
ARES8-CN24H20
  rect 0.61x0.66 smd: 1(-0.9,-0.486) 4(0.9,-0.486) 5(0.9,0.486) 8(-0.9,0.486)
  rect 0.305x0.66 smd: 2(-0.25,-0.486) 3(0.25,-0.486) 6(0.25,0.486) 7(-0.25,0.486)
ARES8-CN24H22
  rect 0.61x0.66 smd: 1(-0.9,-0.486) 4(0.9,-0.486) 5(0.9,0.486) 8(-0.9,0.486)
  rect 0.305x0.66 smd: 2(-0.25,-0.486) 3(0.25,-0.486) 6(0.25,0.486) 7(-0.25,0.486)
AS0A621-J4SB-7H
  round 0.254 hole 1.6 unplated: (-33.4,0)
  round 0.254 hole 1.118 unplated: (33.4,0)
  custom 0.114x0.114 smd: 1(-31.65,-4.1) 2(-31.35,4.1) 3(-31.05,-4.1) 4(-30.75,4.1) 5(-30.45,-4.1) 6(-30.15,4.1) 7(-29.85,-4.1) 8(-29.55,4.1) 9(-29.25,-4.1) 10(-28.95,4.1) 11(-28.65,-4.1) 12(-28.35,4.1) 13(-28.05,-4.1) 14(-27.75,4.1) 15(-27.45,-4.1) 16(-27.15,4.1) 17(-26.85,-4.1) 18(-26.55,4.1) 19(-26.25,-4.1) 20(-25.95,4.1) 21(-25.65,-4.1) 22(-25.35,4.1) 23(-25.05,-4.1) 24(-24.75,4.1) 25(-24.45,-4.1) 26(-24.15,4.1) 27(-23.85,-4.1) 28(-23.55,4.1) 29(-23.25,-4.1) 30(-22.95,4.1) 31(-22.65,-4.1) 32(-22.35,4.1) 33(-22.05,-4.1) 34(-21.75,4.1) 35(-21.45,-4.1) 36(-21.15,4.1) 37(-20.85,-4.1) 38(-20.55,4.1) 39(-20.25,-4.1) 40(-19.95,4.1) 41(-19.65,-4.1) 42(-19.35,4.1) 43(-19.05,-4.1) 44(-18.75,4.1) 45(-18.45,-4.1) 46(-18.15,4.1) 47(-17.85,-4.1) 48(-17.55,4.1) 49(-17.25,-4.1) 50(-16.95,4.1) 51(-16.65,-4.1) 52(-16.35,4.1) 53(-16.05,-4.1) 54(-15.75,4.1) 55(-15.45,-4.1) 56(-15.15,4.1) 57(-14.85,-4.1) 58(-14.55,4.1) 59(-14.25,-4.1) 60(-13.95,4.1) 61(-13.65,-4.1) 62(-13.35,4.1) 63(-13.05,-4.1) 64(-12.75,4.1) 65(-12.45,-4.1) 66(-12.15,4.1) 67(-11.85,-4.1) 68(-11.55,4.1) 69(-11.25,-4.1) 70(-10.95,4.1) 71(-10.65,-4.1) 72(-10.35,4.1) 73(-7.65,-4.1) 74(-7.35,4.1) 75(-7.05,-4.1) 76(-6.75,4.1) 77(-6.45,-4.1) 78(-6.15,4.1) 79(-5.85,-4.1) 80(-5.55,4.1) 81(-5.25,-4.1) 82(-4.95,4.1) 83(-4.65,-4.1) 84(-4.35,4.1) 85(-4.05,-4.1) 86(-3.75,4.1) 87(-3.45,-4.1) 88(-3.15,4.1) 89(-2.85,-4.1) 90(-2.55,4.1) 91(-2.25,-4.1) 92(-1.95,4.1) 93(-1.65,-4.1) 94(-1.35,4.1) 95(-1.05,-4.1) 96(-0.75,4.1) 97(-0.45,-4.1) 98(-0.15,4.1) 99(0.15,-4.1) 100(0.45,4.1) 101(0.75,-4.1) 102(1.05,4.1) 103(1.35,-4.1) 104(1.65,4.1) 105(1.95,-4.1) 106(2.25,4.1) 107(2.55,-4.1) 108(2.85,4.1) 109(3.15,-4.1) 110(3.45,4.1) 111(3.75,-4.1) 112(4.05,4.1) 113(4.35,-4.1) 114(4.65,4.1) 115(4.95,-4.1) 116(5.25,4.1) 117(5.55,-4.1) 118(5.85,4.1) 119(6.15,-4.1) 120(6.45,4.1) 121(6.75,-4.1) 122(7.05,4.1) 123(7.35,-4.1) 124(7.65,4.1) 125(7.95,-4.1) 126(8.25,4.1) 127(8.55,-4.1) 128(8.85,4.1) 129(9.15,-4.1) 130(9.45,4.1) 131(9.75,-4.1) 132(10.05,4.1) 133(10.35,-4.1) 134(10.65,4.1) 135(10.95,-4.1) 136(11.25,4.1) 137(11.55,-4.1) 138(11.85,4.1) 139(12.15,-4.1) 140(12.45,4.1) 141(12.75,-4.1) 142(13.05,4.1) 143(13.35,-4.1) 144(13.65,4.1) 145(13.95,-4.1) 146(14.25,4.1) 147(14.55,-4.1) 148(14.85,4.1) 149(15.15,-4.1) 150(15.45,4.1) 151(15.75,-4.1) 152(16.05,4.1) 153(16.35,-4.1) 154(16.65,4.1) 155(16.95,-4.1) 156(17.25,4.1) 157(17.55,-4.1) 158(17.85,4.1) 159(18.15,-4.1) 160(18.45,4.1) 161(18.75,-4.1) 162(19.05,4.1) 163(19.35,-4.1) 164(19.65,4.1) 165(19.95,-4.1) 166(20.25,4.1) 167(20.55,-4.1) 168(20.85,4.1) 169(21.15,-4.1) 170(21.45,4.1) 171(21.75,-4.1) 172(22.05,4.1) 173(22.35,-4.1) 174(22.65,4.1) 175(22.95,-4.1) 176(23.25,4.1) 177(23.55,-4.1) 178(23.85,4.1) 179(24.15,-4.1) 180(24.45,4.1) 181(24.75,-4.1) 182(25.05,4.1) 183(25.35,-4.1) 184(25.65,4.1) 185(25.95,-4.1) 186(26.25,4.1) 187(26.55,-4.1) 188(26.85,4.1) 189(27.15,-4.1) 190(27.45,4.1) 191(27.75,-4.1) 192(28.05,4.1) 193(28.35,-4.1) 194(28.65,4.1) 195(28.95,-4.1) 196(29.25,4.1) 197(29.55,-4.1) 198(29.85,4.1) 199(30.15,-4.1) 200(30.45,4.1) 201(30.75,-4.1) 202(31.05,4.1) 203(31.35,-4.1) 204(31.65,4.1)
  rect 3.505x4.597 smd: 205(-32.8,12) 206(32.8,12)
ASP-137098-05
  rect 0.737x2.794 smd: 1(-5.715,-2.035) 2(-5.715,2.035) 3(-4.445,-2.035) 4(-4.445,2.035) 5(-3.175,-2.035) 6(-3.175,2.035) 7(-1.905,-2.035) 8(-1.905,2.035) 9(-0.635,-2.035) 10(-0.635,2.035) 11(0.635,-2.035) 12(0.635,2.035) 13(1.905,-2.035) 14(1.905,2.035) 15(3.175,-2.035) 16(3.175,2.035) 17(4.445,-2.035) 18(4.445,2.035) 19(5.715,-2.035) 20(5.715,2.035)
BGA769M24D5H78
  round 0.4 smd: A2(-10.7,11.3) A3(-9.95,11.3) A39(9.95,11.3) A40(10.7,11.3) AA4(-9.2,0) AA5(-8.4,0) AA7(-7.6,0) AA8(-6.8,0) AA10(-6,0) AA11(-5,0) AA13(-4,0) AA15(-3,0) AA17(-2,0) AA19(-1,0) AA21(0,0) AA23(1,0) AA25(2,0) AA27(3,0) AA29(4,0) AA31(5,0) AA32(6,0) AA34(6.8,0) AA35(7.6,0) AA37(8.4,0) AA38(9.2,0) AC4(-9.2,-1.1) AC5(-8.4,-1.1) AC7(-7.6,-1.1) AC8(-6.8,-1.1) AC10(-6,-1.1) AC11(-5,-1) AC13(-4,-1) AC15(-3,-1) AC17(-2,-1) AC19(-1,-1) AC21(0,-1) AC23(1,-1) AC25(2,-1) AC27(3,-1) AC29(4,-1) AC31(5,-1) AC32(6,-1.1) AC34(6.8,-1.1) AC35(7.6,-1.1) AC37(8.4,-1.1) AC38(9.2,-1.1) AE4(-9.2,-2.2) AE5(-8.4,-2.2) AE7(-7.6,-2.2) AE8(-6.8,-2.2) AE10(-6,-2.2) AE11(-5,-2) AE13(-4,-2) AE15(-3,-2) AE17(-2,-2) AE19(-1,-2) AE21(0,-2) AE23(1,-2) AE25(2,-2) AE27(3,-2) AE29(4,-2) AE31(5,-2) AE32(6,-2.2) AE34(6.8,-2.2) AE35(7.6,-2.2) AE37(8.4,-2.2) AE38(9.2,-2.2) AG4(-9.2,-3.3) AG5(-8.4,-3.3) AG7(-7.6,-3.3) AG8(-6.8,-3.3) AG10(-6,-3.3) AG11(-5,-3) AG13(-4,-3) AG15(-3,-3) AG17(-2,-3) AG19(-1,-3) AG21(0,-3) AG23(1,-3) AG25(2,-3) AG27(3,-3) AG29(4,-3) AG31(5,-3) AG32(6,-3.3) AG34(6.8,-3.3) AG35(7.6,-3.3) AG37(8.4,-3.3) AG38(9.2,-3.3) AJ4(-9.2,-4.4) AJ5(-8.4,-4.4) AJ7(-7.6,-4.4) AJ8(-6.8,-4.4) AJ10(-6,-4.4) AJ11(-5,-4) AJ13(-4,-4) AJ15(-3,-4) AJ17(-2,-4) AJ19(-1,-4) AJ21(0,-4) AJ23(1,-4) AJ25(2,-4) AJ27(3,-4) AJ29(4,-4) AJ31(5,-4) AJ32(6,-4.4) AJ34(6.8,-4.4) AJ35(7.6,-4.4) AJ37(8.4,-4.4) AJ38(9.2,-4.4) AL4(-9.2,-5.5) AL5(-8.4,-5.5) AL7(-7.6,-5.5) AL8(-6.8,-5.5) AL10(-6,-5.5) AL11(-5,-5) AL13(-4,-5) AL15(-3,-5) AL17(-2,-5) AL19(-1,-5) AL21(0,-5) AL23(1,-5) AL25(2,-5) AL27(3,-5) AL29(4,-5) AL31(5,-5) AL32(6,-5.5) AL34(6.8,-5.5) AL35(7.6,-5.5) AL37(8.4,-5.5) AL38(9.2,-5.5) AM11(-5.5,-6) AM13(-4.4,-6) AM15(-3.3,-6) AM17(-2.2,-6) AM19(-1.1,-6) AM21(0,-6) AM23(1.1,-6) AM25(2.2,-6) AM27(3.3,-6) AM29(4.4,-6) AM31(5.5,-6) AN4(-9.2,-6.6) AN5(-8.4,-6.6) AN7(-7.6,-6.6) AN8(-6.8,-6.6) AN34(6.8,-6.6) AN35(7.6,-6.6) AN37(8.4,-6.6) AN38(9.2,-6.6) AP11(-5.5,-6.8) AP13(-4.4,-6.8) AP15(-3.3,-6.8) AP17(-2.2,-6.8) AP19(-1.1,-6.8) AP21(0,-6.8) AP23(1.1,-6.8) AP25(2.2,-6.8) AP27(3.3,-6.8) AP29(4.4,-6.8) AP31(5.5,-6.8) AR4(-9.2,-7.7) AR5(-8.4,-7.7) AR7(-7.6,-7.7) AR11(-5.5,-7.6) AR13(-4.4,-7.6) AR15(-3.3,-7.6) AR17(-2.2,-7.6) AR19(-1.1,-7.6) AR21(0,-7.6) AR23(1.1,-7.6) AR25(2.2,-7.6) AR27(3.3,-7.6) AR29(4.4,-7.6) AR31(5.5,-7.6) AR35(7.6,-7.7) AR37(8.4,-7.7) AR38(9.2,-7.7) AU4(-9.2,-8.8) AU7(-7.7,-8.4) AU9(-6.6,-8.4) AU11(-5.5,-8.4) AU13(-4.4,-8.4) AU15(-3.3,-8.4) AU17(-2.2,-8.4) AU19(-1.1,-8.4) AU21(0,-8.4) AU23(1.1,-8.4) AU25(2.2,-8.4) AU27(3.3,-8.4) AU29(4.4,-8.4) AU31(5.5,-8.4) AU33(6.6,-8.4) AU35(7.7,-8.4) AU38(9.2,-8.8) AV7(-7.7,-9.2) AV9(-6.6,-9.2) AV11(-5.5,-9.2) AV13(-4.4,-9.2) AV15(-3.3,-9.2) AV17(-2.2,-9.2) AV19(-1.1,-9.2) AV21(0,-9.2) AV23(1.1,-9.2) AV25(2.2,-9.2) AV27(3.3,-9.2) AV29(4.4,-9.2) AV31(5.5,-9.2) AV33(6.6,-9.2) AV35(7.7,-9.2) AW1(-11.3,-9.95) AW41(11.3,-9.95) AY1(-11.3,-10.7) AY2(-10.6,-10.6) AY40(10.6,-10.6) AY41(11.3,-10.7) B1(-11.3,10.7) B2(-10.6,10.6) B40(10.6,10.6) B41(11.3,10.7) BA2(-10.7,-11.3) BA3(-9.95,-11.3) BA39(9.95,-11.3) BA40(10.7,-11.3) C1(-11.3,9.95) C41(11.3,9.95) D7(-7.7,9.2) D9(-6.6,9.2) D11(-5.5,9.2) D13(-4.4,9.2) D15(-3.3,9.2) D17(-2.2,9.2) D19(-1.1,9.2) D21(0,9.2) D23(1.1,9.2) D25(2.2,9.2) D27(3.3,9.2) D29(4.4,9.2) D31(5.5,9.2) D33(6.6,9.2) D35(7.7,9.2) E4(-9.2,8.8) E7(-7.7,8.4) E9(-6.6,8.4) E11(-5.5,8.4) E13(-4.4,8.4) E15(-3.3,8.4) E17(-2.2,8.4) E19(-1.1,8.4) E21(0,8.4) E23(1.1,8.4) E25(2.2,8.4) E27(3.3,8.4) E29(4.4,8.4) E31(5.5,8.4) E33(6.6,8.4) E35(7.7,8.4) E38(9.2,8.8) G4(-9.2,7.7) G5(-8.4,7.7) G7(-7.6,7.7) G11(-5.5,7.6) G13(-4.4,7.6) G15(-3.3,7.6) G17(-2.2,7.6) G19(-1.1,7.6) G21(0,7.6) G23(1.1,7.6) G25(2.2,7.6) G27(3.3,7.6) G29(4.4,7.6) G31(5.5,7.6) G35(7.6,7.7) G37(8.4,7.7) G38(9.2,7.7) H11(-5.5,6.8) H13(-4.4,6.8) H15(-3.3,6.8) H17(-2.2,6.8) H19(-1.1,6.8) H21(0,6.8) H23(1.1,6.8) H25(2.2,6.8) H27(3.3,6.8) H29(4.4,6.8) H31(5.5,6.8) J4(-9.2,6.6) J5(-8.4,6.6) J7(-7.6,6.6) J8(-6.8,6.6) J34(6.8,6.6) J35(7.6,6.6) J37(8.4,6.6) J38(9.2,6.6) K11(-5.5,6) K13(-4.4,6) K15(-3.3,6) K17(-2.2,6) K19(-1.1,6) K21(0,6) K23(1.1,6) K25(2.2,6) K27(3.3,6) K29(4.4,6) K31(5.5,6) L4(-9.2,5.5) L5(-8.4,5.5) L7(-7.6,5.5) L8(-6.8,5.5) L10(-6,5.5) L11(-5,5) L13(-4,5) L15(-3,5) L17(-2,5) L19(-1,5) L21(0,5) L23(1,5) L25(2,5) L27(3,5) L29(4,5) L31(5,5) L32(6,5.5) L34(6.8,5.5) L35(7.6,5.5) L37(8.4,5.5) L38(9.2,5.5) N4(-9.2,4.4) N5(-8.4,4.4) N7(-7.6,4.4) N8(-6.8,4.4) N10(-6,4.4) N11(-5,4) N13(-4,4) N15(-3,4) N17(-2,4) N19(-1,4) N21(0,4) N23(1,4) N25(2,4) N27(3,4) N29(4,4) N31(5,4) N32(6,4.4) N34(6.8,4.4) N35(7.6,4.4) N37(8.4,4.4) N38(9.2,4.4) R4(-9.2,3.3) R5(-8.4,3.3) R7(-7.6,3.3) R8(-6.8,3.3) R10(-6,3.3) R11(-5,3) R13(-4,3) R15(-3,3) R17(-2,3) R19(-1,3) R21(0,3) R23(1,3) R25(2,3) R27(3,3) R29(4,3) R31(5,3) R32(6,3.3) R34(6.8,3.3) R35(7.6,3.3) R37(8.4,3.3) R38(9.2,3.3) U4(-9.2,2.2) U5(-8.4,2.2) U7(-7.6,2.2) U8(-6.8,2.2) U10(-6,2.2) U11(-5,2) U13(-4,2) U15(-3,2) U17(-2,2) U19(-1,2) U21(0,2) U23(1,2) U25(2,2) U27(3,2) U29(4,2) U31(5,2) U32(6,2.2) U34(6.8,2.2) U35(7.6,2.2) U37(8.4,2.2) U38(9.2,2.2) W4(-9.2,1.1) W5(-8.4,1.1) W7(-7.6,1.1) W8(-6.8,1.1) W10(-6,1.1) W11(-5,1) W13(-4,1) W15(-3,1) W17(-2,1) W19(-1,1) W21(0,1) W23(1,1) W25(2,1) W27(3,1) W29(4,1) W31(5,1) W32(6,1.1) W34(6.8,1.1) W35(7.6,1.1) W37(8.4,1.1) W38(9.2,1.1)
  round 0.3 smd: A4(-9.35,10.95) A5(-8.8,11.3) A6(-8.25,10.95) A7(-7.7,11.3) A8(-7.15,10.95) A9(-6.6,11.3) A10(-6.05,10.95) A11(-5.5,11.3) A12(-4.95,10.95) A13(-4.4,11.3) A14(-3.85,10.95) A15(-3.3,11.3) A16(-2.75,10.95) A17(-2.2,11.3) A18(-1.65,10.95) A19(-1.1,11.3) A20(-0.55,10.95) A21(0,11.3) A22(0.55,10.95) A23(1.1,11.3) A24(1.65,10.95) A25(2.2,11.3) A26(2.75,10.95) A27(3.3,11.3) A28(3.85,10.95) A29(4.4,11.3) A30(4.95,10.95) A31(5.5,11.3) A32(6.05,10.95) A33(6.6,11.3) A34(7.15,10.95) A35(7.7,11.3) A36(8.25,10.95) A37(8.8,11.3) A38(9.35,10.95) AA1(-11.3,0) AA2(-10.6,0) AA3(-9.9,0) AA39(9.9,0) AA40(10.6,0) AA41(11.3,0) AB1(-10.95,-0.55) AB2(-10.25,-0.55) AB40(10.25,-0.55) AB41(10.95,-0.55) AC1(-11.3,-1.1) AC2(-10.6,-1.1) AC3(-9.9,-1.1) AC39(9.9,-1.1) AC40(10.6,-1.1) AC41(11.3,-1.1) AD1(-10.95,-1.65) AD2(-10.25,-1.65) AD40(10.25,-1.65) AD41(10.95,-1.65) AE1(-11.3,-2.2) AE2(-10.6,-2.2) AE3(-9.9,-2.2) AE39(9.9,-2.2) AE40(10.6,-2.2) AE41(11.3,-2.2) AF1(-10.95,-2.75) AF2(-10.25,-2.75) AF40(10.25,-2.75) AF41(10.95,-2.75) AG1(-11.3,-3.3) AG2(-10.6,-3.3) AG3(-9.9,-3.3) AG39(9.9,-3.3) AG40(10.6,-3.3) AG41(11.3,-3.3) AH1(-10.95,-3.85) AH2(-10.25,-3.85) AH40(10.25,-3.85) AH41(10.95,-3.85) AJ1(-11.3,-4.4) AJ2(-10.6,-4.4) AJ3(-9.9,-4.4) AJ39(9.9,-4.4) AJ40(10.6,-4.4) AJ41(11.3,-4.4) AK1(-10.95,-4.95) AK2(-10.25,-4.95) AK40(10.25,-4.95) AK41(10.95,-4.95) AL1(-11.3,-5.5) AL2(-10.6,-5.5) AL3(-9.9,-5.5) AL39(9.9,-5.5) AL40(10.6,-5.5) AL41(11.3,-5.5) AM1(-10.95,-6.05) AM2(-10.25,-6.05) AM40(10.25,-6.05) AM41(10.95,-6.05) AN1(-11.3,-6.6) AN2(-10.6,-6.6) AN3(-9.9,-6.6) AN39(9.9,-6.6) AN40(10.6,-6.6) AN41(11.3,-6.6) AP1(-10.95,-7.15) AP2(-10.25,-7.15) AP40(10.25,-7.15) AP41(10.95,-7.15) AR1(-11.3,-7.7) AR2(-10.6,-7.7) AR3(-9.9,-7.7) AR39(9.9,-7.7) AR40(10.6,-7.7) AR41(11.3,-7.7) AT1(-10.95,-8.25) AT2(-10.25,-8.25) AT40(10.25,-8.25) AT41(10.95,-8.25) AU1(-11.3,-8.8) AU2(-10.6,-8.8) AU3(-9.9,-8.8) AU39(9.9,-8.8) AU40(10.6,-8.8) AU41(11.3,-8.8) AV1(-10.95,-9.35) AV2(-10.25,-9.35) AV40(10.25,-9.35) AV41(10.95,-9.35) AW2(-10.6,-9.9) AW3(-9.9,-9.9) AW5(-8.8,-9.9) AW7(-7.7,-9.9) AW9(-6.6,-9.9) AW11(-5.5,-9.9) AW13(-4.4,-9.9) AW15(-3.3,-9.9) AW17(-2.2,-9.9) AW19(-1.1,-9.9) AW21(0,-9.9) AW23(1.1,-9.9) AW25(2.2,-9.9) AW27(3.3,-9.9) AW29(4.4,-9.9) AW31(5.5,-9.9) AW33(6.6,-9.9) AW35(7.7,-9.9) AW37(8.8,-9.9) AW39(9.9,-9.9) AW40(10.6,-9.9) AY3(-9.9,-10.6) AY4(-9.35,-10.25) AY5(-8.8,-10.6) AY6(-8.25,-10.25) AY7(-7.7,-10.6) AY8(-7.15,-10.25) AY9(-6.6,-10.6) AY10(-6.05,-10.25) AY11(-5.5,-10.6) AY12(-4.95,-10.25) AY13(-4.4,-10.6) AY14(-3.85,-10.25) AY15(-3.3,-10.6) AY16(-2.75,-10.25) AY17(-2.2,-10.6) AY18(-1.65,-10.25) AY19(-1.1,-10.6) AY20(-0.55,-10.25) AY21(0,-10.6) AY22(0.55,-10.25) AY23(1.1,-10.6) AY24(1.65,-10.25) AY25(2.2,-10.6) AY26(2.75,-10.25) AY27(3.3,-10.6) AY28(3.85,-10.25) AY29(4.4,-10.6) AY30(4.95,-10.25) AY31(5.5,-10.6) AY32(6.05,-10.25) AY33(6.6,-10.6) AY34(7.15,-10.25) AY35(7.7,-10.6) AY36(8.25,-10.25) AY37(8.8,-10.6) AY38(9.35,-10.25) AY39(9.9,-10.6) B3(-9.9,10.6) B4(-9.35,10.25) B5(-8.8,10.6) B6(-8.25,10.25) B7(-7.7,10.6) B8(-7.15,10.25) B9(-6.6,10.6) B10(-6.05,10.25) B11(-5.5,10.6) B12(-4.95,10.25) B13(-4.4,10.6) B14(-3.85,10.25) B15(-3.3,10.6) B16(-2.75,10.25) B17(-2.2,10.6) B18(-1.65,10.25) B19(-1.1,10.6) B20(-0.55,10.25) B21(0,10.6) B22(0.55,10.25) B23(1.1,10.6) B24(1.65,10.25) B25(2.2,10.6) B26(2.75,10.25) B27(3.3,10.6) B28(3.85,10.25) B29(4.4,10.6) B30(4.95,10.25) B31(5.5,10.6) B32(6.05,10.25) B33(6.6,10.6) B34(7.15,10.25) B35(7.7,10.6) B36(8.25,10.25) B37(8.8,10.6) B38(9.35,10.25) B39(9.9,10.6) BA4(-9.35,-10.95) BA5(-8.8,-11.3) BA6(-8.25,-10.95) BA7(-7.7,-11.3) BA8(-7.15,-10.95) BA9(-6.6,-11.3) BA10(-6.05,-10.95) BA11(-5.5,-11.3) BA12(-4.95,-10.95) BA13(-4.4,-11.3) BA14(-3.85,-10.95) BA15(-3.3,-11.3) BA16(-2.75,-10.95) BA17(-2.2,-11.3) BA18(-1.65,-10.95) BA19(-1.1,-11.3) BA20(-0.55,-10.95) BA21(0,-11.3) BA22(0.55,-10.95) BA23(1.1,-11.3) BA24(1.65,-10.95) BA25(2.2,-11.3) BA26(2.75,-10.95) BA27(3.3,-11.3) BA28(3.85,-10.95) BA29(4.4,-11.3) BA30(4.95,-10.95) BA31(5.5,-11.3) BA32(6.05,-10.95) BA33(6.6,-11.3) BA34(7.15,-10.95) BA35(7.7,-11.3) BA36(8.25,-10.95) BA37(8.8,-11.3) BA38(9.35,-10.95) C2(-10.6,9.9) C3(-9.9,9.9) C5(-8.8,9.9) C7(-7.7,9.9) C9(-6.6,9.9) C11(-5.5,9.9) C13(-4.4,9.9) C15(-3.3,9.9) C17(-2.2,9.9) C19(-1.1,9.9) C21(0,9.9) C23(1.1,9.9) C25(2.2,9.9) C27(3.3,9.9) C29(4.4,9.9) C31(5.5,9.9) C33(6.6,9.9) C35(7.7,9.9) C37(8.8,9.9) C39(9.9,9.9) C40(10.6,9.9) D1(-10.95,9.35) D2(-10.25,9.35) D40(10.25,9.35) D41(10.95,9.35) E1(-11.3,8.8) E2(-10.6,8.8) E3(-9.9,8.8) E39(9.9,8.8) E40(10.6,8.8) E41(11.3,8.8) F1(-10.95,8.25) F2(-10.25,8.25) F40(10.25,8.25) F41(10.95,8.25) G1(-11.3,7.7) G2(-10.6,7.7) G3(-9.9,7.7) G39(9.9,7.7) G40(10.6,7.7) G41(11.3,7.7) H1(-10.95,7.15) H2(-10.25,7.15) H40(10.25,7.15) H41(10.95,7.15) J1(-11.3,6.6) J2(-10.6,6.6) J3(-9.9,6.6) J39(9.9,6.6) J40(10.6,6.6) J41(11.3,6.6) K1(-10.95,6.05) K2(-10.25,6.05) K40(10.25,6.05) K41(10.95,6.05) L1(-11.3,5.5) L2(-10.6,5.5) L3(-9.9,5.5) L39(9.9,5.5) L40(10.6,5.5) L41(11.3,5.5) M1(-10.95,4.95) M2(-10.25,4.95) M40(10.25,4.95) M41(10.95,4.95) N1(-11.3,4.4) N2(-10.6,4.4) N3(-9.9,4.4) N39(9.9,4.4) N40(10.6,4.4) N41(11.3,4.4) P1(-10.95,3.85) P2(-10.25,3.85) P40(10.25,3.85) P41(10.95,3.85) R1(-11.3,3.3) R2(-10.6,3.3) R3(-9.9,3.3) R39(9.9,3.3) R40(10.6,3.3) R41(11.3,3.3) T1(-10.95,2.75) T2(-10.25,2.75) T40(10.25,2.75) T41(10.95,2.75) U1(-11.3,2.2) U2(-10.6,2.2) U3(-9.9,2.2) U39(9.9,2.2) U40(10.6,2.2) U41(11.3,2.2) V1(-10.95,1.65) V2(-10.25,1.65) V40(10.25,1.65) V41(10.95,1.65) W1(-11.3,1.1) W2(-10.6,1.1) W3(-9.9,1.1) W39(9.9,1.1) W40(10.6,1.1) W41(11.3,1.1) Y1(-10.95,0.55) Y2(-10.25,0.55) Y40(10.25,0.55) Y41(10.95,0.55)
C100PF-10809-L
  round 1.27 hole 0.914: 1(-3.556,5.32) 2(-2.54,6.42) 3(-1.524,5.32) 4(-0.508,6.42) 5(0.508,5.32) 6(1.524,6.42) 7(2.54,5.32) 8(3.556,6.42)
  oval 1.321x3.124 hole 0.711x2.413: 9(-9.325,0) 10(9.325,0)
C402H20
  custom 0.14x0.14 smd: 1(0,0.445) 2(0,-0.445)
C402H22
  custom 0.14x0.14 smd: 1(0,0.445) 2(0,-0.445)
C603
  custom 0.197x0.197 smd: 1(0,0.66) 2(0,-0.66)
C603H36
  custom 0.197x0.197 smd: 1(0,0.66) 2(0,-0.66)
C603H38
  custom 0.197x0.197 smd: 1(0,0.66) 2(0,-0.66)
C603H40
  custom 0.197x0.197 smd: 1(0,0.66) 2(0,-0.66)
C805H38
  rect 1.549x0.94 smd: 1(0,0.838) 2(0,-0.838)
C805H54
  rect 1.549x0.94 smd: 1(0,0.838) 2(0,-0.838)
C805H56
  rect 1.549x0.94 smd: 1(0,0.838) 2(0,-0.838)
C805H58
  rect 1.549x0.94 smd: 1(0,0.838) 2(0,-0.838)
C1206H71
  rect 1.854x1.27 smd: 1(0,1.397) 2(0,-1.397)
C1808H56
  rect 2.286x1.27 smd: 1(0,2.032) 2(0,-2.032)
CON2O-U
  custom 0.159x0.159 smd: 1(0,0.254) 2(0,-0.254)
CS1S-461HN
  round 0.254 hole 1.168 unplated: (-11.5,0)
  round 0.254 hole 1.651 unplated: (9.5,0)
  rect 0.991x1.499 smd: 1(6.88,2.75) 2(4.38,2.75) 3(1.88,2.75) 4(-0.62,2.75) 5(-3.12,2.75) 6(-5.62,2.75) 7(-8.04,2.75) 8(-9.74,2.75) 9(9.38,2.75)
  rect 0.711x1.499 smd: 10(-11.04,2.75) 11(-12.24,2.75)
  rect 1.397x2.794 smd: 12(11.5,1) 13(-13.7,1)
  oval 1.321x4.013 hole 0.61x3.302: 14(13.15,-8.85) 15(-13.15,-8.85)
CT7343H83
  rect 2.413x2.286 smd: 1(0,3.15) 2(0,-3.15)
D402H24
  custom 0.14x0.14 smd: 1(0,0.445) 2(0,-0.445)
DFN10G3-G265175H32
  rect 0.305x0.914 smd: 1(1,1.549) 2(0.5,1.549) 3(0,1.549) 4(-0.5,1.549) 5(-1,1.549) 6(-1,-1.549) 7(-0.5,-1.549) 8(0,-1.549) 9(0.5,-1.549) 10(1,-1.549)
  rect 2.642x1.753 smd: 11(0,0)
DFN10G2510H26
  rect 0.305x0.787 smd: 1(1,0.494) 5(-1,0.494) 6(-1,-0.494) 10(1,-0.494)
  rect 0.254x0.787 smd: 2(0.521,0.494) 4(-0.521,0.494) 7(-0.521,-0.494) 9(0.521,-0.494)
  rect 0.025x0.025 smd: 3(0,0.494)
  rect 0.406x1.753 smd: 8(0,-0.494)
DFN14J3020-G255D85H32
  custom 0.151x0.151 smd: 1(1.2,1.076) 6(-0.8,1.076) 8(-1.2,-1.076) 13(0.8,-1.076)
  rect 0.025x0.025 smd: 2(0.8,1.076) 7(-1.2,1.076) 9(-0.8,-1.076) 14(1.2,-1.076)
  rect 0.203x0.864 smd: 3(0.4,1.076) 4(0,1.076) 5(-0.4,1.076) 10(-0.4,-1.076) 11(0,-1.076) 12(0.4,-1.076)
  rect 2.54x0.838 smd: 15(0,0)
DO214AAAKH97
  rect 2.261x1.905 smd: A(0,2.35) K(0,-2.35)
FL4S030HT6R300-DT
  rect 0.305x1.295 smd: 1(-11.6,5.65) 2(-10.8,5.65) 3(-10,5.65) 4(-9.2,5.65) 5(-8.4,5.65) 6(-7.6,5.65) 7(-6.8,5.65) 8(-6,5.65) 9(-5.2,5.65) 10(-4.4,5.65) 11(-3.6,5.65) 12(-2.8,5.65) 13(-2,5.65) 14(-1.2,5.65) 15(-0.4,5.65) 16(0.4,5.65) 17(1.2,5.65) 18(2,5.65) 19(2.8,5.65) 20(3.6,5.65) 21(4.4,5.65) 22(5.2,5.65) 23(6,5.65) 24(6.8,5.65) 25(7.6,5.65) 26(8.4,5.65) 27(9.2,5.65) 28(10,5.65) 29(10.8,5.65) 30(11.6,5.65)
  rect 1.803x2.21 smd: 31(-13.94,0) 32(13.94,0)
G6179HT0321-001
  rect 0.635x2.108 smd: 1(1.905,3.466) 2(0.635,3.466) 3(-0.635,3.466) 4(-1.905,3.466) 5(-1.905,-3.466) 6(-0.635,-3.466) 7(0.635,-3.466) 8(1.905,-3.466)
GAP-CLOSE-PWR
  rect 0.66x0.762 smd: 1(-0.305,0) 2(0.305,0)
GAP-CLOSE-PWR-3
  rect 0.66x0.762 smd: 1(-0.305,0) 2(0.305,0)
HOLE197R166
  round 5.004 hole 4.216: 1(0,0)
HOLE256R126
  round 6.502 hole 3.2: 1(0,0)
HOLE296R182
  round 7.518 hole 4.623: 1(0,0)
HOLE335R115
  round 8.509 hole 2.921: 1(0,0)
L1608-UH38
  custom 0.197x0.197 smd: 1(0,0.66) 2(0,-0.66)
L2520-D820H41
  rect 2.261x1.422 smd: 1(0,0.907) 2(0,-0.907)
L7066-1830-UH119
  rect 3.505x2.921 smd: 1(0,2.78) 2(0,-2.78)
L7066-1830-UH158
  rect 3.505x2.921 smd: 1(0,2.78) 2(0,-2.78)
L125100-4P-1H37
  rect 0.762x0.432 smd: 1(0.625,0.341) 2(-0.625,0.341) 3(-0.625,-0.341) 4(0.625,-0.341)
L125100-4P-4H28
  rect 0.762x0.432 smd: 1(-0.625,0.341) 2(0.625,0.341) 3(0.625,-0.341) 4(-0.625,-0.341)
L686647-127318H119
  rect 3.683x2.413 smd: 1(0,2.986) 2(0,-2.986)
LED3015-1A2K-3PH44
  rect 0.813x0.991 smd: 1A(0,1.4) 2K(0,-1.4)
  rect 0.61x0.991 smd: 3(0.4,0)
LED3020-3P-19H44
  rect 1.499x0.991 smd: 1(0,1.5) 3(0,-1.5)
  rect 0.889x0.889 smd: 2(0.65,0)
LFQFN52J6-G4D8-1H40
  rect 0.203x0.533 smd: 1(2.4,2.911) 13(-2.4,2.911) 27(-2.4,-2.911) 39(2.4,-2.911)
  rect 0.203x0.584 smd: 2(2,2.911) 3(1.6,2.911) 4(1.2,2.911) 5(0.8,2.911) 6(0.4,2.911) 7(0,2.911) 8(-0.4,2.911) 9(-0.8,2.911) 10(-1.2,2.911) 11(-1.6,2.911) 12(-2,2.911) 28(-2,-2.911) 29(-1.6,-2.911) 30(-1.2,-2.911) 31(-0.8,-2.911) 32(-0.4,-2.911) 33(0,-2.911) 34(0.4,-2.911) 35(0.8,-2.911) 36(1.2,-2.911) 37(1.6,-2.911) 38(2,-2.911)
  rect 0.533x0.203 smd: 14(-2.911,2.4) 26(-2.911,-2.4) 40(2.911,-2.4) 52(2.911,2.4)
  rect 0.584x0.203 smd: 15(-2.911,2) 16(-2.911,1.6) 17(-2.911,1.2) 18(-2.911,0.8) 19(-2.911,0.4) 20(-2.911,0) 21(-2.911,-0.4) 22(-2.911,-0.8) 23(-2.911,-1.2) 24(-2.911,-1.6) 25(-2.911,-2) 41(2.911,-2) 42(2.911,-1.6) 43(2.911,-1.2) 44(2.911,-0.8) 45(2.911,-0.4) 46(2.911,0) 47(2.911,0.4) 48(2.911,0.8) 49(2.911,1.2) 50(2.911,1.6) 51(2.911,2)
  rect 4.801x4.801 smd: 53(0,0)
LQFP128H63
  rect 0.203x1.524 smd: 1(6.2,7.747) 2(5.8,7.747) 3(5.4,7.747) 4(5,7.747) 5(4.6,7.747) 6(4.2,7.747) 7(3.8,7.747) 8(3.4,7.747) 9(3,7.747) 10(2.6,7.747) 11(2.2,7.747) 12(1.8,7.747) 13(1.4,7.747) 14(0.999,7.747) 15(0.599,7.747) 16(0.199,7.747) 17(-0.199,7.747) 18(-0.599,7.747) 19(-0.999,7.747) 20(-1.4,7.747) 21(-1.8,7.747) 22(-2.2,7.747) 23(-2.6,7.747) 24(-3,7.747) 25(-3.4,7.747) 26(-3.8,7.747) 27(-4.2,7.747) 28(-4.6,7.747) 29(-5,7.747) 30(-5.4,7.747) 31(-5.8,7.747) 32(-6.2,7.747) 65(-6.2,-7.747) 66(-5.8,-7.747) 67(-5.4,-7.747) 68(-5,-7.747) 69(-4.6,-7.747) 70(-4.2,-7.747) 71(-3.8,-7.747) 72(-3.4,-7.747) 73(-3,-7.747) 74(-2.6,-7.747) 75(-2.2,-7.747) 76(-1.8,-7.747) 77(-1.4,-7.747) 78(-0.999,-7.747) 79(-0.599,-7.747) 80(-0.199,-7.747) 81(0.199,-7.747) 82(0.599,-7.747) 83(0.999,-7.747) 84(1.4,-7.747) 85(1.8,-7.747) 86(2.2,-7.747) 87(2.6,-7.747) 88(3,-7.747) 89(3.4,-7.747) 90(3.8,-7.747) 91(4.2,-7.747) 92(4.6,-7.747) 93(5,-7.747) 94(5.4,-7.747) 95(5.8,-7.747) 96(6.2,-7.747)
  rect 1.524x0.203 smd: 33(-7.747,6.2) 34(-7.747,5.8) 35(-7.747,5.4) 36(-7.747,5) 37(-7.747,4.6) 38(-7.747,4.2) 39(-7.747,3.8) 40(-7.747,3.4) 41(-7.747,3) 42(-7.747,2.6) 43(-7.747,2.2) 44(-7.747,1.8) 45(-7.747,1.4) 46(-7.747,0.999) 47(-7.747,0.599) 48(-7.747,0.199) 49(-7.747,-0.199) 50(-7.747,-0.599) 51(-7.747,-0.999) 52(-7.747,-1.4) 53(-7.747,-1.8) 54(-7.747,-2.2) 55(-7.747,-2.6) 56(-7.747,-3) 57(-7.747,-3.4) 58(-7.747,-3.8) 59(-7.747,-4.2) 60(-7.747,-4.6) 61(-7.747,-5) 62(-7.747,-5.4) 63(-7.747,-5.8) 64(-7.747,-6.2) 97(7.747,-6.2) 98(7.747,-5.8) 99(7.747,-5.4) 100(7.747,-5) 101(7.747,-4.6) 102(7.747,-4.2) 103(7.747,-3.8) 104(7.747,-3.4) 105(7.747,-3) 106(7.747,-2.6) 107(7.747,-2.2) 108(7.747,-1.8) 109(7.747,-1.4) 110(7.747,-0.999) 111(7.747,-0.599) 112(7.747,-0.199) 113(7.747,0.199) 114(7.747,0.599) 115(7.747,0.999) 116(7.747,1.4) 117(7.747,1.8) 118(7.747,2.2) 119(7.747,2.6) 120(7.747,3) 121(7.747,3.4) 122(7.747,3.8) 123(7.747,4.2) 124(7.747,4.6) 125(7.747,5) 126(7.747,5.4) 127(7.747,5.8) 128(7.747,6.2)
MSOP8-1G189157H43
  rect 0.356x1.524 smd: 1(-0.975,-2.059) 2(-0.325,-2.059) 3(0.325,-2.059) 4(0.975,-2.059) 5(0.975,2.059) 6(0.325,2.059) 7(-0.325,2.059) 8(-0.975,2.059)
  rect 1.88x1.575 smd: 9(0,0)
MSOP8-1H44
  rect 0.356x1.524 smd: 1(-0.975,-2.055) 2(-0.325,-2.055) 3(0.325,-2.055) 4(0.975,-2.055) 5(0.975,2.055) 6(0.325,2.055) 7(-0.325,2.055) 8(-0.975,2.055)
NFSA0-S6705-TP40
  round 0.254 hole 1.651 unplated: (-10,0)
  round 0.254 hole 1.168 unplated: (10,0)
  rect 0.305x1.549 smd: 1(9.25,-5.275) 2(9,2.275) 3(8.75,-5.275) 4(8.5,2.275) 5(8.25,-5.275) 6(8,2.275) 7(7.75,-5.275) 16(5.5,2.275) 17(5.25,-5.275) 18(5,2.275) 19(4.75,-5.275) 20(4.5,2.275) 21(4.25,-5.275) 22(4,2.275) 23(3.75,-5.275) 24(3.5,2.275) 25(3.25,-5.275) 26(3,2.275) 27(2.75,-5.275) 28(2.5,2.275) 29(2.25,-5.275) 30(2,2.275) 31(1.75,-5.275) 32(1.5,2.275) 33(1.25,-5.275) 34(1,2.275) 35(0.75,-5.275) 36(0.5,2.275) 37(0.25,-5.275) 38(0,2.275) 39(-0.25,-5.275) 40(-0.5,2.275) 41(-0.75,-5.275) 42(-1,2.275) 43(-1.25,-5.275) 44(-1.5,2.275) 45(-1.75,-5.275) 46(-2,2.275) 47(-2.25,-5.275) 48(-2.5,2.275) 49(-2.75,-5.275) 50(-3,2.275) 51(-3.25,-5.275) 52(-3.5,2.275) 53(-3.75,-5.275) 54(-4,2.275) 55(-4.25,-5.275) 56(-4.5,2.275) 57(-4.75,-5.275) 58(-5,2.275) 59(-5.25,-5.275) 60(-5.5,2.275) 61(-5.75,-5.275) 62(-6,2.275) 63(-6.25,-5.275) 64(-6.5,2.275) 65(-6.75,-5.275) 66(-7,2.275) 67(-7.25,-5.275) 68(-7.5,2.275) 69(-7.75,-5.275) 70(-8,2.275) 71(-8.25,-5.275) 72(-8.5,2.275) 73(-8.75,-5.275) 74(-9,2.275) 75(-9.25,-5.275)
  rect 1.194x2.743 smd: 76(10.35,-4.5) 77(-10.35,-4.5)
